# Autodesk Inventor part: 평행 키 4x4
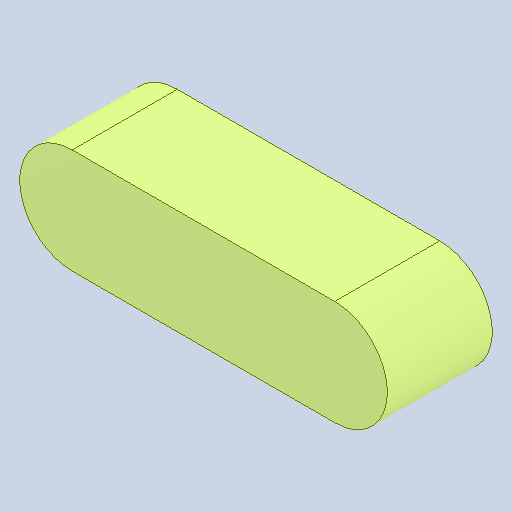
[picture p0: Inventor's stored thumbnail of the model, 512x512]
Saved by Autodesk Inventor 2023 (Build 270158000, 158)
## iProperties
Created: 2025-04
Part Number: 평행 키 4x4
Material: 강철, 연강
Document SubType Name: Modeling
Designer: user
Density: 7.86 g/cm^3
Appearance: 기본값
Author: jhkim
Revision Number: 1
Sending System: Autodesk Inventor 2026
Preprocessor: ST-DEVELOPER v20.1
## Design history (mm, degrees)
feature "솔리드1"
node "솔리드2"
